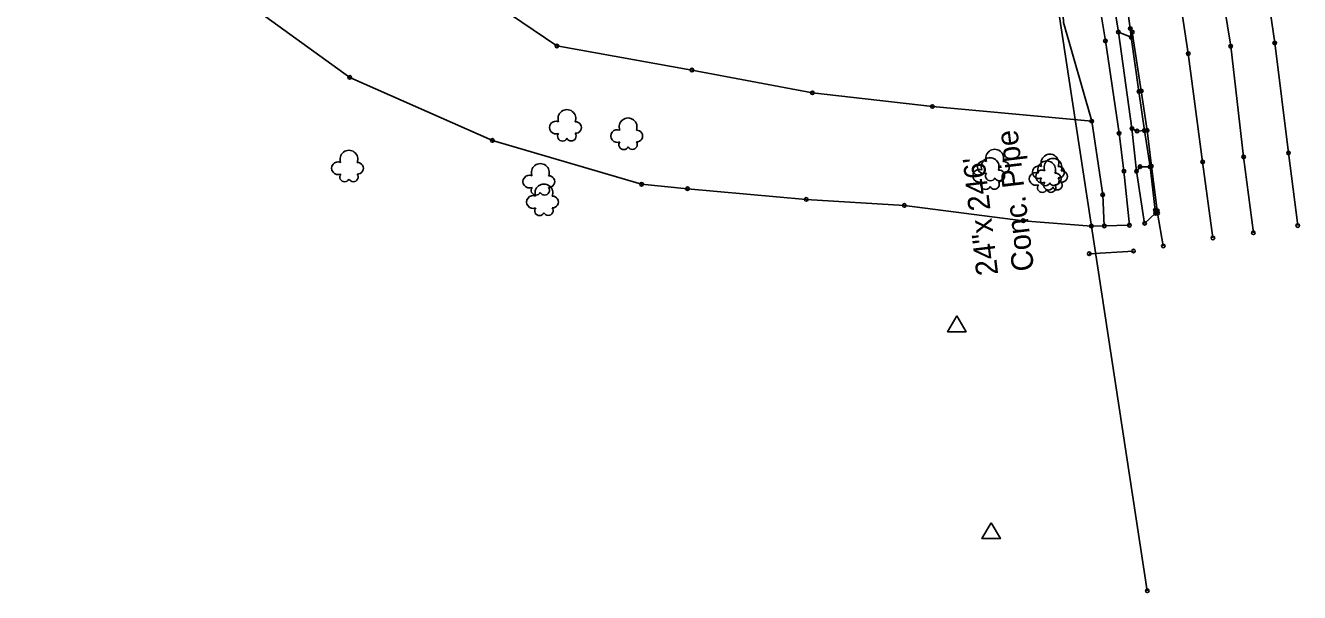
# Model space of a CAD drawing. Extents: x 21481721 to 21494985, y 8063982 to 8084842.
# Drawn here: x 21487809.7 to 21488161.5, y 8074923 to 8075079.6 of the extents above; entities that cross this region are included whole.
import ezdxf

# ---------------------------------------------------------------- set-up
doc = ezdxf.new("R2010")
doc.units = 0
for name, color, linetype in [('Drainage', 7, 'Continuous'), ('EXT_BL', 7, 'Continuous'), ('EXT_C', 7, 'Continuous'), ('EXT_CU', 7, 'Continuous'), ('EXT_ENP', 7, 'Continuous'), ('EXT_ENT', 7, 'Continuous'), ('EXT_EP', 7, 'Continuous'), ('EXT_GU', 7, 'Continuous'), ('EXT_SH', 7, 'Continuous'), ('EXT_SWK', 7, 'Continuous'), ('SurControl', 7, 'Continuous'), ('SurNaturalCells', 7, 'Continuous'), ('SurPointsNonDTM', 7, 'Continuous'), ('SurSurveyPoints', 7, 'Continuous'), ('Text', 7, 'Continuous')]:
    doc.layers.add(name, color=color, linetype=linetype)

msp = doc.modelspace()

# ---------------------------------------------------------------- linework, layer by layer
at = {"layer": 'Drainage'}
msp.add_lwpolyline([(21488082.26, 8075166.99), (21488119.44, 8074923.49)], dxfattribs=at)
at = {"layer": 'EXT_BL'}
for points in [[(21488090.05, 8075209.72), (21488083.79, 8075196.97), (21488087.59, 8075180.36), (21488090.9, 8075162.26), (21488093.56, 8075140.02), (21488095.56, 8075119.4), (21488095.13, 8075105.8), (21488096.33, 8075080.43), (21488104.11, 8075053.16), (21488107.13, 8075032.83), (21488107.57, 8075024.24)], [(21488108.38, 8075207.07), (21488113.55, 8075177.43), (21488114.9, 8075169.23), (21488115.72, 8075164.23), (21488116.59, 8075159.19), (21488121.77, 8075129.5), (21488126.26, 8075101.13), (21488130.75, 8075071.82), (21488134.72, 8075041.91), (21488137.54, 8075020.92)], [(21488132.99, 8075208.17), (21488137.39, 8075181.27), (21488138.65, 8075172.84), (21488139.41, 8075167.86), (21488140.16, 8075163.05), (21488145.37, 8075132.64), (21488150.36, 8075104.26), (21488154.62, 8075074.76), (21488158.43, 8075044.39), (21488160.97, 8075024.33)], [(21488104.11, 8075053.16), (21488060.1, 8075057.21), (21488026.96, 8075060.99), (21487993.7, 8075067.26), (21487956.41, 8075073.93), (21487921.18, 8075097.88), (21487878.26, 8075124.79), (21487850.62, 8075156.33), (21487846.7, 8075177.74)], [(21488104, 8075024.19), (21488085.19, 8075025.67), (21488052.36, 8075029.9), (21488025.25, 8075031.54), (21487992.49, 8075034.52), (21487979.79, 8075035.75), (21487938.6, 8075047.85), (21487899.23, 8075065.23), (21487852.86, 8075098.85), (21487814.73, 8075142.38), (21487809.68, 8075175.41)]]:
    msp.add_lwpolyline(points, dxfattribs=at)
at = {"layer": 'EXT_C'}
msp.add_lwpolyline([(21488120.86, 8075207.63), (21488125.18, 8075179.72), (21488127.51, 8075166.09), (21488128.19, 8075161.24), (21488133.19, 8075130.91), (21488137.71, 8075103.12), (21488142.46, 8075073.86), (21488146.04, 8075043.29), (21488148.72, 8075022.35)], dxfattribs=at)
at = {"layer": 'EXT_CU'}
msp.add_lwpolyline([(21488114.73, 8075078.75), (21488114.99, 8075076.33), (21488117.13, 8075061.37), (21488118.63, 8075050.57), (21488120.19, 8075040.58), (21488121.65, 8075028.63), (21488121.7, 8075027.74)], dxfattribs=at)
at = {"layer": 'EXT_ENP'}
for points in [[(21488111.46, 8075077.76), (21488114.99, 8075076.33)], [(21488118.7, 8075024.94), (21488121.7, 8075027.74)], [(21488104, 8075024.19), (21488107.57, 8075024.24), (21488114.49, 8075024.43)]]:
    msp.add_lwpolyline(points, dxfattribs=at)
at = {"layer": 'EXT_ENT'}
msp.add_lwpolyline([(21488115.62, 8075017.3), (21488103.4, 8075016.56)], dxfattribs=at)
at = {"layer": 'EXT_EP'}
msp.add_lwpolyline([(21488122.27, 8075027.73), (21488123.85, 8075018.69)], dxfattribs=at)
at = {"layer": 'EXT_GU'}
msp.add_lwpolyline([(21488102.6, 8075157.33), (21488105.44, 8075139.29), (21488109.15, 8075118.54), (21488111.29, 8075104.02), (21488111.18, 8075103.02), (21488110.92, 8075102.68), (21488112.94, 8075091.81), (21488114.73, 8075078.75), (21488115.3, 8075077.75), (21488117.77, 8075061.5), (21488119.37, 8075050.61), (21488120.56, 8075040.74), (21488122.18, 8075028.45), (21488122.27, 8075027.73), (21488121.7, 8075027.74)], dxfattribs=at)
at = {"layer": 'EXT_SH'}
for points in [[(21488118.63, 8075050.57), (21488116.63, 8075050.41), (21488115.21, 8075051.13)], [(21488116.46, 8075039.34), (21488117.45, 8075040.59), (21488120.19, 8075040.58)]]:
    msp.add_lwpolyline(points, dxfattribs=at)
at = {"layer": 'EXT_SWK'}
for points in [[(21488118.7, 8075024.94), (21488116.46, 8075039.34), (21488115.21, 8075051.13), (21488111.46, 8075077.76), (21488107.83, 8075100.24), (21488107.59, 8075102.22), (21488103.86, 8075101.54)], [(21488114.49, 8075024.43), (21488112.99, 8075039.36), (21488111.65, 8075049.81), (21488107.88, 8075075.32), (21488105.26, 8075091.45), (21488103.86, 8075101.54)]]:
    msp.add_lwpolyline(points, dxfattribs=at)
at = {"layer": 'SurControl'}
for points in [[(21488066.85, 8074999.43), (21488069.4, 8074995.02), (21488064.3, 8074995.02)], [(21488076.32, 8074942.27), (21488078.86, 8074937.87), (21488073.77, 8074937.87)]]:
    msp.add_lwpolyline(points, close=True, dxfattribs=at)
at = {"layer": 'SurNaturalCells'}
for centre, radius, start, end in [((21487959.18, 8075053.91), 2.46, 338.2051, 201.7949), ((21487956.16, 8075051.4), 1.76, 65.4824, 294.5175), ((21487961.57, 8075051.4), 1.6, 265.9982, 94.0018), ((21487973.06, 8075049.06), 1.76, 65.4824, 294.5175), ((21487976.07, 8075051.58), 2.46, 338.2051, 201.7949), ((21487957.96, 8075048.99), 1.34, 142.7501, 335.3223), ((21487960.37, 8075049.03), 1.34, 206.5242, 35.4033), ((21487974.86, 8075046.65), 1.34, 142.7501, 335.3223), ((21487977.27, 8075046.69), 1.34, 206.5242, 35.4033), ((21487978.47, 8075049.06), 1.6, 265.9982, 94.0018), ((21487898.99, 8075042.67), 2.46, 338.2051, 201.7949), ((21488077.31, 8075042.95), 2.46, 338.2051, 201.7949), ((21488092.53, 8075041.58), 2.46, 338.2051, 201.7949), ((21487895.98, 8075040.16), 1.76, 65.4824, 294.5175), ((21487901.39, 8075040.16), 1.6, 265.9982, 94.0018), ((21487951.83, 8075038.98), 2.46, 338.2051, 201.7949), ((21488074.3, 8075040.44), 1.76, 65.4824, 294.5175), ((21488076.03, 8075040.59), 2.46, 338.2051, 201.7949), ((21488079.71, 8075040.44), 1.6, 265.9982, 94.0018), ((21488089.51, 8075039.07), 1.76, 65.4824, 294.5175), ((21488091.64, 8075039.73), 2.46, 338.2051, 201.7949), ((21488093.39, 8075040.39), 2.46, 338.2051, 201.7949), ((21488094.92, 8075039.07), 1.6, 265.9982, 94.0018), ((21487897.78, 8075037.75), 1.34, 142.7501, 335.3223), ((21487900.19, 8075037.78), 1.34, 206.5242, 35.4033), ((21487948.81, 8075036.47), 1.76, 65.4824, 294.5175), ((21487954.22, 8075036.47), 1.6, 265.9982, 94.0018), ((21488073.02, 8075038.08), 1.76, 65.4824, 294.5175), ((21488076.1, 8075038.03), 1.34, 142.7501, 335.3223), ((21488078.51, 8075038.06), 1.34, 206.5242, 35.4033), ((21488078.43, 8075038.08), 1.6, 265.9982, 94.0018), ((21488088.62, 8075037.22), 1.76, 65.4824, 294.5175), ((21488090.38, 8075037.88), 1.76, 65.4824, 294.5175), ((21488091.31, 8075036.66), 1.34, 142.7501, 335.3223), ((21488093.72, 8075036.7), 1.34, 206.5242, 35.4033), ((21488094.03, 8075037.22), 1.6, 265.9982, 94.0018), ((21488095.79, 8075037.88), 1.6, 265.9982, 94.0018), ((21487950.61, 8075034.06), 1.34, 142.7501, 335.3223), ((21487952.83, 8075033.35), 2.46, 338.2051, 201.7949), ((21487953.02, 8075034.09), 1.34, 206.5242, 35.4033), ((21488074.81, 8075035.67), 1.34, 142.7501, 335.3223), ((21488077.23, 8075035.71), 1.34, 206.5242, 35.4033), ((21488090.42, 8075034.81), 1.34, 142.7501, 335.3223), ((21488092.17, 8075035.47), 1.34, 142.7501, 335.3223), ((21488092.83, 8075034.85), 1.34, 206.5242, 35.4033), ((21488094.58, 8075035.51), 1.34, 206.5242, 35.4033), ((21487949.82, 8075030.84), 1.76, 65.4824, 294.5175), ((21487955.23, 8075030.84), 1.6, 265.9982, 94.0018), ((21487951.62, 8075028.43), 1.34, 142.7501, 335.3223), ((21487954.03, 8075028.47), 1.34, 206.5242, 35.4033)]:
    msp.add_arc(centre, radius, start, end, dxfattribs=at)
at = {"layer": 'SurPointsNonDTM'}
msp.add_circle((21488119.44, 8074923.49), 0.5, dxfattribs=at)
at = {"layer": 'SurSurveyPoints'}
for centre in [(21488114.73, 8075078.75), (21488114.73, 8075078.75), (21488107.88, 8075075.32), (21488111.46, 8075077.76), (21488111.46, 8075077.76), (21488114.99, 8075076.33), (21488114.99, 8075076.33), (21488115.3, 8075077.75), (21487956.41, 8075073.93), (21488130.75, 8075071.82), (21488142.46, 8075073.86), (21488154.62, 8075074.76), (21487899.23, 8075065.23), (21487993.7, 8075067.26), (21488026.96, 8075060.99), (21488117.13, 8075061.37), (21488117.77, 8075061.5), (21488060.1, 8075057.21), (21488104.11, 8075053.16), (21488104.11, 8075053.16), (21488115.21, 8075051.13), (21488115.21, 8075051.13), (21488116.63, 8075050.41), (21488118.63, 8075050.57), (21488118.63, 8075050.57), (21488119.37, 8075050.61), (21487938.6, 8075047.85), (21488111.65, 8075049.81), (21488146.04, 8075043.29), (21488158.43, 8075044.39), (21488117.45, 8075040.59), (21488120.19, 8075040.58), (21488120.19, 8075040.58), (21488120.56, 8075040.74), (21488134.72, 8075041.91), (21488112.99, 8075039.36), (21488116.46, 8075039.34), (21488116.46, 8075039.34), (21487979.79, 8075035.75), (21487992.49, 8075034.52), (21488107.13, 8075032.83), (21488025.25, 8075031.54), (21488052.36, 8075029.9), (21488085.19, 8075025.67), (21488121.65, 8075028.63), (21488121.7, 8075027.74), (21488121.7, 8075027.74), (21488121.7, 8075027.74), (21488122.18, 8075028.45), (21488122.27, 8075027.73), (21488122.27, 8075027.73), (21488104, 8075024.19), (21488104, 8075024.19), (21488107.57, 8075024.24), (21488107.57, 8075024.24), (21488114.49, 8075024.43), (21488114.49, 8075024.43), (21488118.7, 8075024.94), (21488118.7, 8075024.94), (21488148.72, 8075022.35), (21488160.97, 8075024.33), (21488123.85, 8075018.69), (21488137.54, 8075020.92), (21488103.4, 8075016.56), (21488115.62, 8075017.3)]:
    msp.add_circle(centre, 0.5, dxfattribs=at)

# ---------------------------------------------------------------- texts
at = {"layer": 'Text'}
for s, p in [('Conc. Pipe', (21488088.21, 8075012.05)), ('24"x 246\'', (21488078.28, 8075010.86))]:
    msp.add_text(s, height=6, rotation=96.8101, dxfattribs=at).set_placement(p)

doc.saveas('drawing.dxf')
